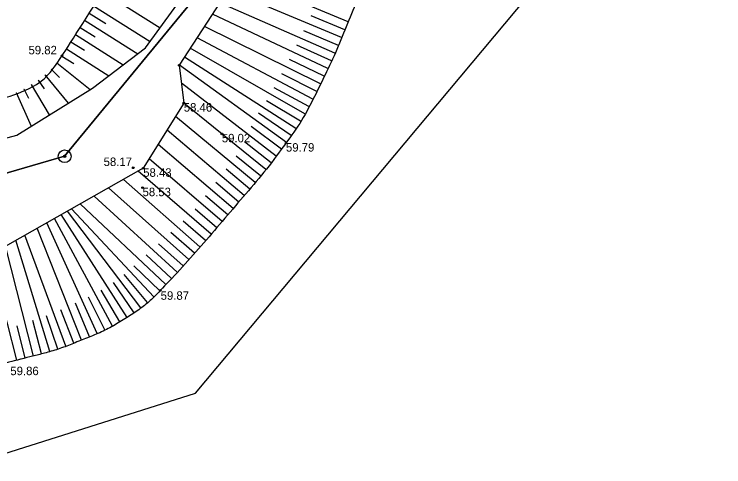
# Model space of a CAD drawing. Extents: x 616607 to 617499, y 408385 to 409695.
# Drawn here: x 616937.6 to 616979.44, y 408564.49 to 408591.17 of the extents above; entities that cross this region are included whole.
import ezdxf

# ---------------------------------------------------------------- set-up
doc = ezdxf.new("R2010")
doc.units = 0
for name, color, linetype in [('HIDG_GRAV_####_####_#', 7, 'Continuous'), ('RAMI_UZMR_####_####_#', 7, 'Continuous'), ('RELJ_AATZ_####_TKST_#', 7, 'Continuous'), ('RELJ_ELEM_####_####_#', 7, 'Continuous'), ('RELJ_NOGA_####_####_#', 7, 'Continuous'), ('ROBZ_IERR_####_####_#', 7, 'Continuous'), ('ROBZ_ROBP_####_####_#', 7, 'Continuous'), ('ROBZ_UZMR_####_####_#', 7, 'Continuous')]:
    doc.layers.add(name, color=color, linetype=linetype)

# ---------------------------------------------------------------- blocks, each defined once
blk = doc.blocks.new('PKT')
at = {"layer": 'RELJ_ELEM_####_####_#'}
blk.add_circle((0, 0), 0.05, dxfattribs=at)
blk = doc.blocks.new('KUPICA')
at = {"layer": 'ROBZ_ROBP_####_####_#'}
for radius in [0.375, 0.0702, 0.0702]:
    blk.add_circle((0, 0), radius, dxfattribs=at)

msp = doc.modelspace()

# ---------------------------------------------------------------- linework, layer by layer
at = {"layer": 'HIDG_GRAV_####_####_#'}
for points in [[(616768.796, 408535.775), (616917.84, 408577.602), (616920.619, 408579.054), (616921.042, 408581.087), (616920.637, 408583.341), (616920.568, 408585.209), (616921.519, 408586.112), (616924.38, 408586.959), (616926.829, 408586.782), (616930.695, 408584.537), (616934.052, 408583.069), (616937.754, 408584.05), (616942.21, 408586.817), (616945.351, 408589.192), (616956.708, 408604.801)], [(616957.621, 408604.01), (616947.332, 408588.16), (616947.6, 408585.931), (616945.208, 408582.089), (616935.727, 408576.737), (616858.974, 408555.268)]]:
    msp.add_lwpolyline(points, dxfattribs=at)
at = {"layer": 'RAMI_UZMR_####_####_#'}
msp.add_lwpolyline([(616666.426, 408467.691), (616675.529, 408457.882), (616687.228, 408463.356), (616723.888, 408465.775), (616753.554, 408507.232), (616948.282, 408568.831), (616981.528, 408608.531), (617014.563, 408672.892), (617101.571, 408748.246), (617213.472, 409074.039)], dxfattribs=at)
at = {"layer": 'RELJ_NOGA_####_####_#'}
for p, q in [((616957.295, 408590.716), (616950.768, 408593.454)), ((616942.819, 408592.511), (616946.211, 408590.375)), ((616956.909, 408589.794), (616950.212, 408592.597)), ((616956.516, 408588.874), (616949.726, 408591.848)), ((616942.285, 408591.665), (616945.62, 408589.562)), ((616942.018, 408591.242), (616943.006, 408590.618)), ((616956.103, 408587.964), (616949.285, 408591.17)), ((616957.102, 408590.255), (616955.118, 408591.086)), ((616941.751, 408590.819), (616944.883, 408588.838)), ((616941.751, 408590.819), (616941.752, 408590.819)), ((616957.295, 408590.716), (616957.294, 408590.717)), ((616941.484, 408590.397), (616942.375, 408589.832)), ((616941.484, 408590.397), (616941.484, 408590.397)), ((616955.666, 408587.064), (616948.816, 408590.447)), ((616956.714, 408589.333), (616954.688, 408590.195)), ((616957.102, 408590.255), (616957.102, 408590.255)), ((616941.216, 408589.974), (616944.028, 408588.192)), ((616941.216, 408589.974), (616941.217, 408589.974)), ((616955.213, 408586.173), (616948.381, 408589.777)), ((616956.909, 408589.794), (616956.908, 408589.794)), ((616940.948, 408589.552), (616941.744, 408589.047)), ((616940.948, 408589.552), (616940.949, 408589.552)), ((616956.313, 408588.417), (616954.268, 408589.341)), ((616956.714, 408589.333), (616956.714, 408589.333)), ((616940.68, 408589.13), (616943.173, 408587.545)), ((616940.68, 408589.13), (616940.681, 408589.13)), ((616954.733, 408585.296), (616947.983, 408589.163)), ((616940.412, 408588.708), (616941.107, 408588.259)), ((616940.412, 408588.708), (616940.412, 408588.708)), ((616954.216, 408584.439), (616947.645, 408588.643)), ((616955.886, 408587.513), (616953.838, 408588.505)), ((616956.516, 408588.874), (616956.515, 408588.875)), ((616940.118, 408588.304), (616942.072, 408586.731)), ((616940.118, 408588.304), (616940.119, 408588.303)), ((616953.655, 408583.612), (616947.343, 408588.178)), ((616956.313, 408588.417), (616956.313, 408588.418)), ((616939.784, 408587.933), (616940.273, 408587.45)), ((616939.784, 408587.933), (616939.784, 408587.933)), ((616955.442, 408586.617), (616953.384, 408587.658)), ((616956.103, 408587.964), (616956.102, 408587.964)), ((616939.017, 408587.293), (616939.376, 408586.778)), ((616939.017, 408587.293), (616939.017, 408587.292)), ((616939.414, 408587.596), (616940.791, 408585.936)), ((616939.414, 408587.596), (616939.415, 408587.595)), ((616955.886, 408587.513), (616955.886, 408587.513)), ((616938.598, 408587.02), (616939.657, 408585.232)), ((616938.598, 408587.02), (616938.598, 408587.02)), ((616953.056, 408582.812), (616947.459, 408587.104)), ((616954.977, 408585.732), (616952.931, 408586.842)), ((616955.666, 408587.064), (616955.665, 408587.065)), ((616937.71, 408586.562), (616938.592, 408584.57)), ((616937.71, 408586.562), (616937.71, 408586.561)), ((616938.161, 408586.778), (616938.451, 408586.216)), ((616938.161, 408586.778), (616938.161, 408586.777)), ((616955.442, 408586.617), (616955.442, 408586.617)), ((616954.48, 408584.864), (616952.475, 408586.069)), ((616955.213, 408586.173), (616955.212, 408586.173)), ((616952.438, 408582.025), (616947.595, 408585.923)), ((616954.977, 408585.732), (616954.976, 408585.732)), ((616953.942, 408584.022), (616952.005, 408585.334)), ((616954.733, 408585.296), (616954.732, 408585.296)), ((616951.806, 408581.25), (616947.105, 408585.135)), ((616954.48, 408584.864), (616954.479, 408584.865)), ((616951.164, 408580.483), (616946.611, 408584.341)), ((616953.358, 408583.21), (616951.567, 408584.549)), ((616954.216, 408584.439), (616954.216, 408584.44)), ((616953.942, 408584.022), (616953.941, 408584.022)), ((616950.516, 408579.722), (616946.088, 408583.502)), ((616952.749, 408582.417), (616951.182, 408583.653)), ((616953.655, 408583.612), (616953.654, 408583.613)), ((616953.358, 408583.21), (616953.358, 408583.21)), ((616949.866, 408578.962), (616945.558, 408582.65)), ((616952.123, 408581.636), (616950.692, 408582.806)), ((616953.056, 408582.812), (616953.055, 408582.812)), ((616952.749, 408582.417), (616952.749, 408582.417)), ((616949.214, 408578.204), (616944.919, 408581.926)), ((616951.486, 408580.866), (616950.098, 408582.029)), ((616952.438, 408582.025), (616952.437, 408582.026)), ((616948.555, 408577.451), (616944.039, 408581.429)), ((616952.123, 408581.636), (616952.123, 408581.637)), ((616950.841, 408580.102), (616949.494, 408581.249)), ((616951.806, 408581.25), (616951.805, 408581.251)), ((616947.891, 408576.704), (616943.165, 408580.936)), ((616951.486, 408580.866), (616951.486, 408580.866)), ((616947.218, 408575.964), (616942.316, 408580.456)), ((616950.191, 408579.342), (616948.881, 408580.462)), ((616951.164, 408580.483), (616951.163, 408580.484)), ((616945.839, 408574.517), (616940.983, 408579.704)), ((616946.538, 408575.231), (616941.482, 408579.986)), ((616950.516, 408579.722), (616950.515, 408579.722)), ((616950.841, 408580.102), (616950.84, 408580.102)), ((616944.256, 408573.298), (616940.377, 408579.362)), ((616945.076, 408573.871), (616940.748, 408579.571)), ((616949.541, 408578.582), (616948.269, 408579.68)), ((616950.191, 408579.342), (616950.191, 408579.342)), ((616942.499, 408572.347), (616939.521, 408578.879)), ((616943.394, 408572.792), (616939.979, 408579.137)), ((616948.885, 408577.827), (616947.563, 408578.982)), ((616949.866, 408578.962), (616949.866, 408578.962)), ((616941.577, 408571.96), (616938.952, 408578.557)), ((616949.541, 408578.582), (616949.54, 408578.582)), ((616940.643, 408571.601), (616938.218, 408578.143)), ((616948.224, 408577.077), (616946.838, 408578.309)), ((616949.214, 408578.204), (616949.213, 408578.205)), ((616939.696, 408571.282), (616937.688, 408577.844)), ((616947.555, 408576.333), (616946.112, 408577.642)), ((616948.885, 408577.827), (616948.885, 408577.827)), ((616938.73, 408571.022), (616937.096, 408577.51)), ((616948.555, 408577.451), (616948.555, 408577.452)), ((616937.76, 408570.779), (616936.159, 408576.981)), ((616946.879, 408575.596), (616945.386, 408576.984)), ((616948.224, 408577.077), (616948.223, 408577.077)), ((616947.891, 408576.704), (616947.89, 408576.705)), ((616946.194, 408574.868), (616944.663, 408576.337)), ((616947.218, 408575.964), (616947.218, 408575.964)), ((616947.555, 408576.333), (616947.555, 408576.333)), ((616945.465, 408574.184), (616944.09, 408575.823)), ((616946.879, 408575.596), (616946.879, 408575.597)), ((616944.672, 408573.575), (616943.45, 408575.349)), ((616946.538, 408575.231), (616946.537, 408575.232)), ((616943.83, 408573.037), (616942.736, 408574.902)), ((616946.194, 408574.868), (616946.194, 408574.868)), ((616942.95, 408572.562), (616941.991, 408574.496)), ((616945.839, 408574.517), (616945.838, 408574.517)), ((616942.04, 408572.147), (616941.221, 408574.131)), ((616945.076, 408573.871), (616945.075, 408573.871)), ((616945.465, 408574.184), (616945.465, 408574.184)), ((616941.111, 408571.777), (616940.352, 408573.749)), ((616944.672, 408573.575), (616944.672, 408573.576)), ((616939.215, 408571.146), (616938.694, 408573.12)), ((616940.172, 408571.434), (616939.507, 408573.402)), ((616943.83, 408573.037), (616943.83, 408573.037)), ((616944.256, 408573.298), (616944.256, 408573.299)), ((616938.245, 408570.901), (616937.77, 408572.81)), ((616943.394, 408572.792), (616943.394, 408572.793)), ((616942.499, 408572.347), (616942.498, 408572.348)), ((616942.95, 408572.562), (616942.95, 408572.562)), ((616941.111, 408571.777), (616941.111, 408571.778)), ((616941.577, 408571.96), (616941.576, 408571.961)), ((616942.04, 408572.147), (616942.04, 408572.147)), ((616940.172, 408571.434), (616940.172, 408571.435)), ((616940.643, 408571.601), (616940.643, 408571.602)), ((616938.73, 408571.022), (616938.73, 408571.023)), ((616939.215, 408571.146), (616939.215, 408571.146)), ((616939.696, 408571.282), (616939.696, 408571.283)), ((616937.76, 408570.779), (616937.76, 408570.78)), ((616938.245, 408570.901), (616938.245, 408570.901))]:
    msp.add_line(p, q, dxfattribs=at)
msp.add_open_spline([(616975.731, 408606.41), (616971.71, 408604.144), (616967.689, 408601.878), (616963.668, 408599.612), (616962.341, 408598.864), (616961.192, 408597.791), (616960.311, 408596.511), (616959.39, 408595.173), (616958.675, 408593.776), (616958.002, 408592.329), (616957.302, 408590.825), (616956.736, 408589.272), (616956.015, 408587.778), (616955.313, 408586.324), (616954.582, 408584.882), (616953.626, 408583.572), (616952.496, 408582.025), (616951.261, 408580.593), (616950.022, 408579.143), (616948.785, 408577.695), (616947.537, 408576.278), (616946.22, 408574.895), (616945.626, 408574.271), (616944.957, 408573.742), (616944.225, 408573.278), (616943.451, 408572.788), (616942.648, 408572.387), (616941.804, 408572.051), (616941, 408571.73), (616940.2, 408571.414), (616939.368, 408571.187), (616938.69, 408571.002), (616938.005, 408570.852), (616937.329, 408570.663), (616918.615, 408565.441), (616899.903, 408560.204), (616881.253, 408554.75), (616874.57, 408552.796), (616867.991, 408550.484), (616861.269, 408548.669), (616855.483, 408547.106), (616849.688, 408545.577), (616843.9, 408544.023), (616838.111, 408542.469), (616832.323, 408540.916), (616826.537, 408539.352), (616816.497, 408536.637), (616806.51, 408533.737), (616796.541, 408530.774), (616791.553, 408529.292), (616786.584, 408527.751), (616781.609, 408526.226), (616776.622, 408524.697), (616771.656, 408523.11), (616766.688, 408521.515), (616762.607, 408520.204), (616758.677, 408518.521), (616754.775, 408516.687), (616750.921, 408514.875), (616747.341, 408512.653), (616743.915, 408510.109), (616740.341, 408507.454), (616736.942, 408504.677), (616733.801, 408501.555), (616732.131, 408499.895), (616730.49, 408498.223), (616728.926, 408496.468), (616728.114, 408495.556), (616727.318, 408494.632), (616726.518, 408493.709), (616725.695, 408492.76), (616724.91, 408491.864), (616724.122, 408490.803), (616723.665, 408490.187), (616723.18, 408489.459), (616723.332, 408488.764), (616723.537, 408487.829), (616723.949, 408486.896), (616724.213, 408485.954), (616724.975, 408483.236), (616725.742, 408480.486), (616726.381, 408477.738), (616726.631, 408476.667), (616726.554, 408475.507), (616726.221, 408474.429), (616726.043, 408473.855), (616725.77, 408473.346), (616725.415, 408472.86), (616725.226, 408472.602), (616725.032, 408472.37), (616724.813, 408472.14), (616724.582, 408471.898), (616724.347, 408471.683), (616724.071, 408471.48), (616723.783, 408471.268), (616723.475, 408471.091), (616723.13, 408471.039), (616722.812, 408470.991), (616722.494, 408470.986), (616722.176, 408470.982), (616721.543, 408470.975), (616720.901, 408471.154), (616720.278, 408471.02), (616716.569, 408470.219), (616712.93, 408469.339), (616709.261, 408468.478), (616707.424, 408468.047), (616705.589, 408467.613), (616703.751, 408467.182), (616701.927, 408466.754), (616700.076, 408466.424), (616698.236, 408466.115), (616695.42, 408465.64), (616692.315, 408465.565), (616689.691, 408467.073), (616684.319, 408470.158), (616679.892, 408473.486), (616675.008, 408476.777), (616674.831, 408476.896), (616674.652, 408477.012), (616674.483, 408477.14), (616674.175, 408477.376), (616674.46, 408477.978), (616674.696, 408478.288), (616675.427, 408479.251), (616676.165, 408480.2), (616676.939, 408481.135), (616677.893, 408482.289), (616678.812, 408483.429), (616679.848, 408484.532), (616681.078, 408485.839), (616682.698, 408486.726), (616684.412, 408487.237), (616686.183, 408487.764), (616687.958, 408488.143), (616689.768, 408488.401), (616691.642, 408488.668), (616693.528, 408488.826), (616695.398, 408489.116), (616696.323, 408489.26), (616697.239, 408489.444), (616698.155, 408489.647), (616699.054, 408489.848), (616699.912, 408490.166), (616700.785, 408490.476), (616703.122, 408491.305), (616705.613, 408491.942), (616707.248, 408494.043), (616707.429, 408494.275), (616707.474, 408494.537), (616707.552, 408494.798), (616707.628, 408495.051), (616707.711, 408495.3), (616707.761, 408495.559), (616707.86, 408496.068), (616707.943, 408496.577), (616707.977, 408497.092), (616708.044, 408498.12), (616708.108, 408499.147), (616708.168, 408500.175), (616708.254, 408501.63), (616708.34, 408503.085), (616708.414, 408504.54), (616708.488, 408505.998), (616708.403, 408507.461), (616708.436, 408508.92), (616708.468, 408510.38), (616708.539, 408511.837), (616708.686, 408513.293), (616708.76, 408514.026), (616708.887, 408514.749), (616709.039, 408515.47), (616709.116, 408515.834), (616709.208, 408516.193), (616709.297, 408516.554), (616709.387, 408516.92), (616709.487, 408517.278), (616709.619, 408517.635), (616710.681, 408520.51), (616712.959, 408522.898), (616715.736, 408524.335), (616718.688, 408525.863), (616721.668, 408526.887), (616724.792, 408527.643), (616730.078, 408528.922), (616735.359, 408530.207), (616740.655, 408531.436), (616749.901, 408533.581), (616759.244, 408535.317), (616768.413, 408537.779), (616798.7, 408545.91), (616828.618, 408555.288), (616858.746, 408563.964), (616877.646, 408569.406), (616896.581, 408574.731), (616915.501, 408580.089), (616916.131, 408580.267), (616916.803, 408580.127), (616917.44, 408580.402), (616917.832, 408580.571), (616918.181, 408580.992), (616918.136, 408581.394), (616918.071, 408581.969), (616918.005, 408582.544), (616917.94, 408583.119), (616917.87, 408583.733), (616917.799, 408584.347), (616917.73, 408584.96), (616917.674, 408585.454), (616917.97, 408585.948), (616918.384, 408586.3), (616918.906, 408586.742), (616919.445, 408586.959), (616920.02, 408587.218), (616920.568, 408587.465), (616921.093, 408587.698), (616921.676, 408587.899), (616922.792, 408588.284), (616923.918, 408588.529), (616925.044, 408588.565), (616925.938, 408588.594), (616926.854, 408588.454), (616927.734, 408588.123), (616928.677, 408587.768), (616929.526, 408587.359), (616930.432, 408586.999), (616931.324, 408586.645), (616932.223, 408586.313), (616933.127, 408585.998), (616933.97, 408585.704), (616934.935, 408585.706), (616935.807, 408585.922), (616937.564, 408586.355), (616939.443, 408587.201), (616940.422, 408588.724), (616944.438, 408594.972), (616948.27, 408601.228), (616952.11, 408607.531)], degree=3, dxfattribs=at)
at = {"layer": 'ROBZ_IERR_####_####_#'}
msp.add_lwpolyline([(617055.284, 408797.783), (617087.528, 408757.04), (616999.181, 408676.019), (616968.565, 408608.405), (616958.517, 408604.593), (616940.576, 408582.801), (616889.795, 408568.012), (616805.459, 408543.657), (616730.494, 408522.344), (616717.135, 408556.579)], dxfattribs=at)
at = {"layer": 'ROBZ_UZMR_####_####_#'}
msp.add_lwpolyline([(616704.998, 408460.626), (616695.309, 408466.84), (616688.046, 408471.498), (616708.653, 408488.203), (616730.494, 408522.344), (616805.459, 408543.657), (616889.795, 408568.012), (616940.576, 408582.801), (616958.517, 408604.593), (616968.565, 408608.405), (616974.837, 408605.827), (616993.227, 408598.268)], dxfattribs=at)

# ---------------------------------------------------------------- block references
at = {"layer": 'RELJ_ELEM_####_####_#'}
for p in [(616940.422, 408588.724), (616947.332, 408588.16), (616947.6, 408585.931), (616949.845, 408584.119), (616953.626, 408583.572), (616944.621, 408582.122), (616945.208, 408582.089), (616945.169, 408580.946), (616946.22, 408574.895)]:
    msp.add_blockref('PKT', p, dxfattribs=at)
at = {"layer": 'ROBZ_ROBP_####_####_#'}
msp.add_blockref('KUPICA', (616940.576, 408582.801), dxfattribs=at)

# ---------------------------------------------------------------- texts
at = {"layer": 'RELJ_AATZ_####_TKST_#'}
for s, p in [('59.82', (616938.443, 408588.807)), ('58.46', (616947.6, 408585.431)), ('59.02', (616949.845, 408583.619)), ('59.79', (616953.626, 408583.072)), ('58.17', (616942.874, 408582.224)), ('58.43', (616945.208, 408581.589)), ('58.53', (616945.169, 408580.446)), ('59.87', (616946.237, 408574.339)), ('59.86', (616937.373, 408569.895))]:
    msp.add_text(s, height=0.5, dxfattribs=at).set_placement(p)

doc.saveas('drawing.dxf')
